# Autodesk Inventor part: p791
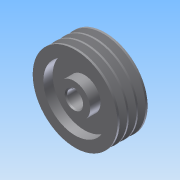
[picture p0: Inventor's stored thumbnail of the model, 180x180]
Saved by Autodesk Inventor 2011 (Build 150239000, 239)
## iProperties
Created: 2014-02
Part Number: p791
Document SubType Name: Modeling
Designer: Administrator
Density: 1 g/cm^3
Author: Administrator
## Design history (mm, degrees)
sketch "草图1"
  geometry: L1 (0, 26)-(0, -26); L2 (-73.5, 26)-(-73.5, 22.5); L3 (-55, -26)-(-55, -19.631); L4 (-55, -10)-(-28, -10); L5 (-21.738, 0)-(-93.823, 0); L6 (-55, 10)-(-28, 10); L7 (-28, -26)-(-28, -10); L8 (-28, 10)-(-28, 26); L9 (-55, -19.631)-(-55, -10); L10 (-55, 10)-(-55, 26); L11 (0, -26)-(-28, -26); L12 (-55, -26)-(-73.5, -26); L13 (0, 26)-(-28, 26); L14 (-55, 26)-(-73.5, 26); L15 (-70, -32.361)-(-70, 39.906); L16 (-61, 16)-(-61, 18.439); L17 (-77.504, 16)-(-58.603, 16); L18 (-73.5, 22.5)-(-61, 18.439); L19 (-61, 16)-(-61, 13.561); L20 (-73.5, 9.5)-(-61, 13.561); L21 (-73.5, -6.5)-(-61, -2.439); L22 (-61, 0)-(-61, -2.439); L23 (-61, 0)-(-61, 2.439); L24 (-73.5, 6.5)-(-61, 2.439); L25 (-73.5, 6.5)-(-73.5, 9.5); L26 (-73.5, -6.5)-(-73.5, -9.5); L27 (-73.5, -9.5)-(-61, -13.561); L28 (-61, -16)-(-61, -13.561); L29 (-61, -16)-(-61, -18.439); L30 (-73.5, -22.5)-(-61, -18.439); L31 (-73.5, -26)-(-73.5, -22.5); 2 further points
  constraints: 62 end point, 16 perpendicular, 10 symmetric about line, 3 parallel, 2 horizontal alignment, 1 coincident, 1 midpoint, 1 point on line, 1 vertical
  dimensions: "d0" = 52 distance of L1.start L1.end; "d30" = 20 distance between parallel lines of L6 L4; "d31" = 56 diameter of L8 L1; "d32" = 110 diameter of L10 L1; "d33" = 147 diameter of L2 L1; "d34" = 70 distance between parallel lines of L1 L15; "d39" = 12.5 distance from line of L2.start L16; "d40" = 3.5 distance of L2.start L2.end; "d41" = 10 distance from line of L2.start L17; "d42" = 72 deg angle of L16 L18; "d43" = 16 distance between parallel lines of L5 L17; "d44" = 72 deg angle of L23 L24; "d45" = 13 distance of L2.end L20.start (derived)
revolve "旋转2" sketch "草图1" stored, may be unused: angle "d46" = 90 deg
sketch "草图7"
  geometry: C1 r 28 at (0, 0) reference
extrude "拉伸6" join sketch "草图7" distance "d47" = 2; taper "d48" = 0 deg
sketch "草图8"
  geometry: C1 r 28 at (0, 0) reference
extrude "拉伸7" join sketch "草图8" distance "d49" = 2; taper "d50" = 0 deg
hole "Hole1" diameter "d53" = 28; stored, may be unused: countersink angle "d57" = 90 deg, drill point angle "d59" = 118 deg; dims "d51" = 10, "d52" = 10, "d54" = 6, "d55" = 4, "d56" = 2, "d58" = 8
sketch "草图9"
  geometry: L1 (-4, 17.3)-(4, 17.3); L2 (4, 17.3)-(4, 10.935); L3 (4, 10.935)-(-4, 10.935); L4 (-4, 10.935)-(-4, 17.3); L5 (0, 0)-(17.943, 0); C1 r 14 at (0, 0) reference; C2 r 28 at (0, 0) reference; 1 further point
  constraints: 10 end point, 2 parallel, 2 perpendicular, 1 horizontal, 1 midpoint, 1 vertical alignment
  dimensions: "d60" = 8 distance of L1.start L1.end; "d61" = 17.3 distance between parallel lines of L1 L5
extrude "拉伸8" cut sketch "草图9" stored distance "d62" = 2; taper "d63" = 0 deg
chamfer "倒角1" distance "d64" = 2; stored, may be unused: second distance "d65" = 2, angle "d66" = 45 deg
chamfer "倒角2" distance "d67" = 2; stored, may be unused: second distance "d68" = 2, angle "d69" = 45 deg
node "实体2"
other parameters: "d28" = 56
